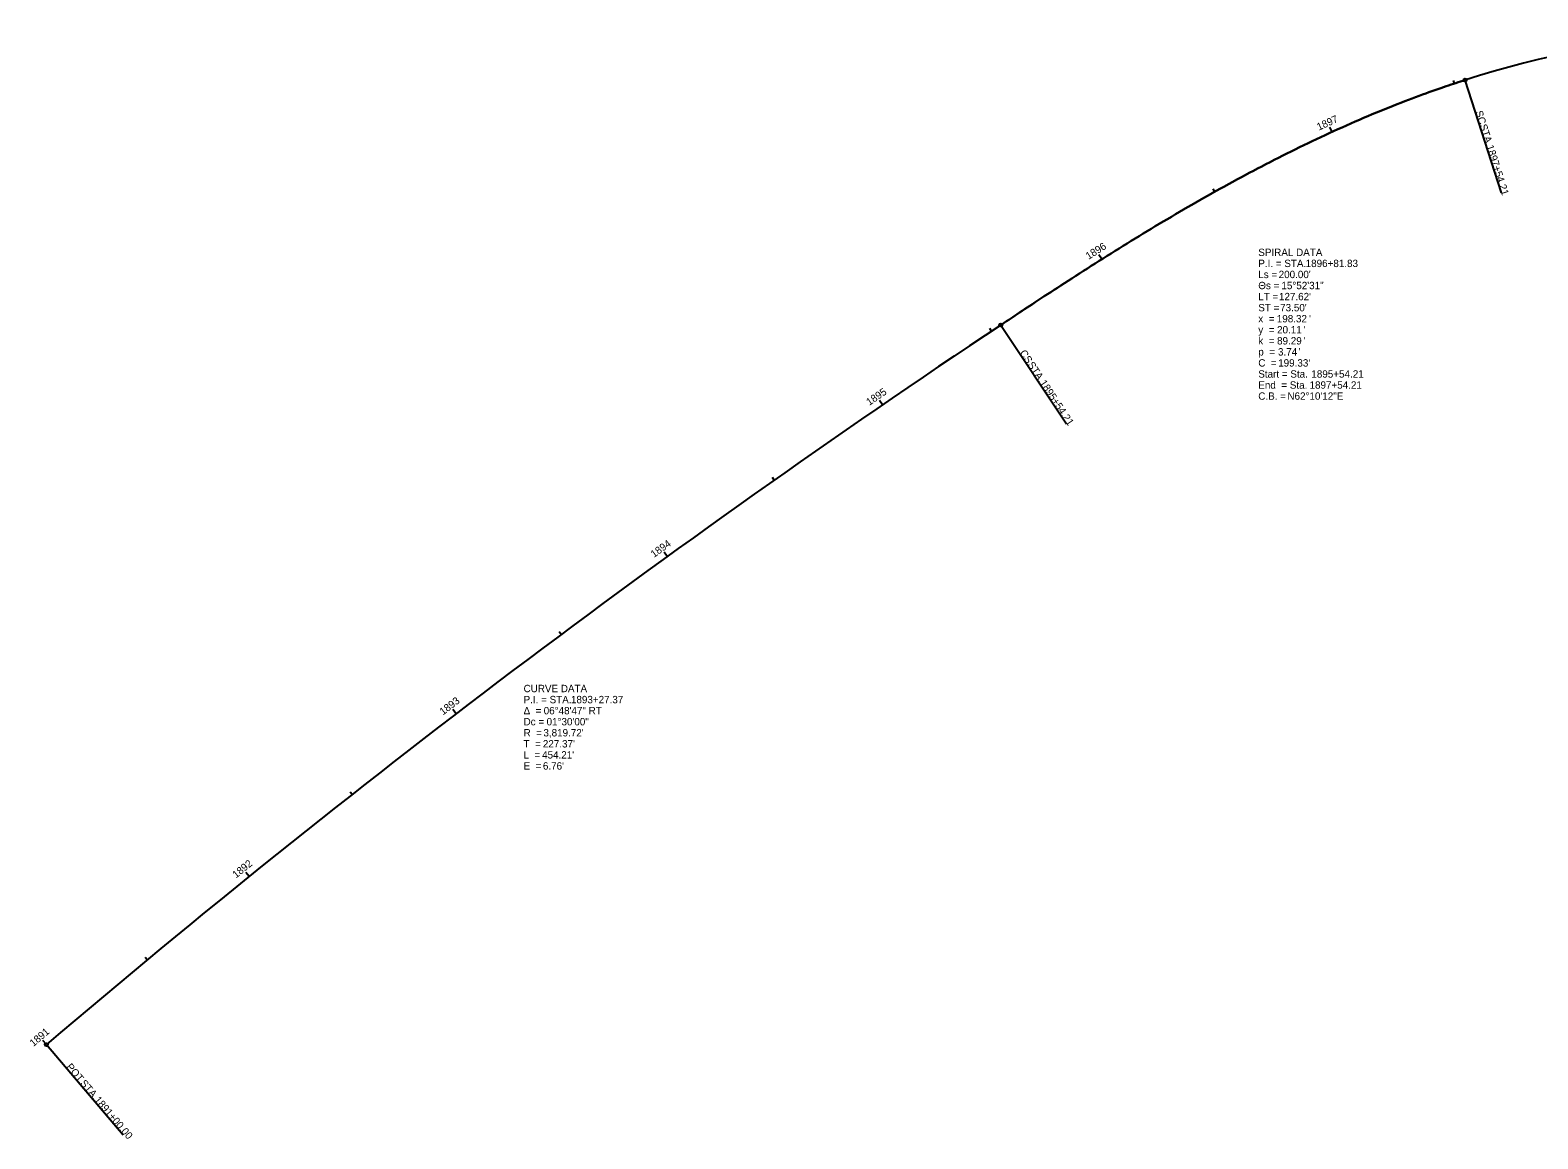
# Model space of a CAD drawing. Extents: x 200995 to 202108, y 391921 to 392784.
# Drawn here: x 200995 to 201568, y 392358 to 392779 of the extents above; entities that cross this region are included whole.
import ezdxf

# ---------------------------------------------------------------- set-up
doc = ezdxf.new("R2010")
doc.units = 0
for name, color, linetype in [('_CIVIL_CONSTRUCTION', 7, 'Continuous'), ('Default', 7, 'Continuous'), ('GE_X_Alignment', 7, 'Continuous'), ('GE_X_Alignment_100_Bearings', 7, 'Continuous'), ('SV_X_Mon_Cells_Found_Text', 7, 'Continuous')]:
    doc.layers.add(name, color=color, linetype=linetype)

msp = doc.modelspace()

# ---------------------------------------------------------------- linework, layer by layer
at = {"layer": '_CIVIL_CONSTRUCTION'}
for centre, radius, start, end in [((201661.28, 392380.6), 398.57, 2.7335, 107.7438), ((203478.39, 389486.33), 3819.72, 123.61908, 130.43223)]:
    msp.add_arc(centre, radius, start, end, dxfattribs=at)
msp.add_open_spline([(201363.53, 392667.15), (201365.52, 392668.47), (201369.48, 392671.1), (201377.43, 392676.35), (201387.4, 392682.86), (201399.42, 392690.58), (201411.53, 392698.17), (201423.73, 392705.6), (201436.04, 392712.84), (201448.48, 392719.87), (201461.05, 392726.65), (201473.78, 392733.15), (201486.65, 392739.34), (201499.69, 392745.18), (201512.89, 392750.65), (201524.03, 392754.85), (201533.02, 392757.99), (201537.54, 392759.49), (201539.81, 392760.21)], degree=3, dxfattribs=at)
at = {"layer": 'Default'}
msp.add_arc((203478.39, 389486.33), 3819.72, 123.61908, 130.43223, dxfattribs=at)
msp.add_open_spline([(201539.81, 392760.21), (201537.54, 392759.49), (201533.02, 392757.99), (201524.03, 392754.85), (201512.89, 392750.65), (201499.69, 392745.18), (201486.65, 392739.34), (201473.78, 392733.15), (201461.05, 392726.65), (201448.48, 392719.87), (201436.04, 392712.84), (201423.73, 392705.6), (201411.53, 392698.17), (201399.42, 392690.58), (201387.4, 392682.86), (201377.43, 392676.35), (201369.48, 392671.1), (201365.52, 392668.47), (201363.53, 392667.15)], degree=3, dxfattribs=at)
at = {"layer": 'GE_X_Alignment'}
for p, q in [((201539.81, 392760.21), (201553.53, 392717.35)), ((201363.53, 392667.15), (201388.45, 392629.68)), ((201001.12, 392393.8), (201030.31, 392359.55))]:
    msp.add_line(p, q, dxfattribs=at)
for centre in [(201539.81, 392760.21), (201363.53, 392667.15), (201001.12, 392393.8)]:
    msp.add_circle(centre, 0.6, dxfattribs=at)
at = {"layer": 'GE_X_Alignment_100_Bearings'}
for p, q in [((201535.81, 392758.91), (201535.43, 392760.05)), ((201489.34, 392740.51), (201488.51, 392742.33)), ((201444.82, 392717.78), (201444.24, 392718.83)), ((201401.91, 392692.13), (201400.85, 392693.82)), ((201360.03, 392664.82), (201359.36, 392665.82)), ((201318.61, 392636.82), (201317.48, 392638.47)), ((201277.55, 392608.28), (201276.86, 392609.26)), ((201236.88, 392579.2), (201235.7, 392580.82)), ((201196.58, 392549.6), (201195.87, 392550.56)), ((201156.68, 392519.47), (201155.47, 392521.06)), ((201117.18, 392488.82), (201116.44, 392489.76)), ((201078.08, 392457.65), (201076.82, 392459.21)), ((201039.39, 392425.98), (201038.63, 392426.9)), ((201001.12, 392393.8), (200999.82, 392395.32))]:
    msp.add_line(p, q, dxfattribs=at)

# ---------------------------------------------------------------- texts
at = {"layer": 'GE_X_Alignment'}
for s, rotation, p in [('SC', 287.7438, (201543.72, 392748.12)), (' STA. ', 287.7438, (201545.05, 392743.97)), ('1897+54.21', 287.7438, (201547.89, 392735.09)), ('CS', 303.6191, (201370.6, 392656.59)), (' STA. ', 303.6191, (201373.02, 392652.96)), ('1895+54.21', 303.6191, (201378.18, 392645.2)), ('POT', 310.4322, (201008.47, 392385.24)), (' STA. ', 310.4322, (201013.09, 392379.81)), ('1891+00.00', 310.4322, (201019.14, 392372.72))]:
    msp.add_text(s, height=2.8, rotation=rotation, dxfattribs=at).set_placement(p)
at = {"layer": 'GE_X_Alignment_100_Bearings'}
for s, rotation, p in [('1897', 24.5907, (201484.34, 392740.97)), ('1896', 32.2573, (201396.88, 392691.91)), ('1895', 34.4322, (201313.63, 392636.44)), ('1894', 35.9322, (201231.85, 392578.65)), ('1893', 37.4322, (201151.74, 392518.83)), ('1892', 38.9322, (201073.14, 392456.88)), ('1891', 40.4322, (200996.2, 392392.89))]:
    msp.add_text(s, height=2.8, rotation=rotation, dxfattribs=at).set_placement(p)
at = {"layer": 'SV_X_Mon_Cells_Found_Text'}
for s, p in [('SPIRAL DATA', (201461.34, 392693.37)), ('P.I. = STA. ', (201461.34, 392689.17)), ('Ls = ', (201461.34, 392684.97)), ("200.00'", (201469.08, 392684.97)), ('1896+81.83', (201479.33, 392689.17)), ('Θs = ', (201461.34, 392680.77)), ('15°52\'31"', (201470.12, 392680.77)), ('ST = ', (201461.34, 392672.37)), ('LT = ', (201461.34, 392676.57)), ("127.62'", (201469.19, 392676.57)), ("73.50'", (201469.64, 392672.37)), ('x  = ', (201461.34, 392668.17)), ('198.32', (201468.37, 392668.17)), ("'", (201480.62, 392668.17)), ('y  = ', (201461.34, 392663.97)), ('20.11', (201468.47, 392663.97)), ("'", (201478.49, 392663.97)), ('k  = ', (201461.34, 392659.77)), ('89.29', (201468.47, 392659.77)), ('3.74', (201468.82, 392655.57)), ("'", (201476.6, 392655.57)), ("'", (201478.49, 392659.77)), ('C  = ', (201461.34, 392651.37)), ('p  = ', (201461.34, 392655.57)), ("199.33'", (201468.89, 392651.37)), ('Start = Sta. ', (201461.34, 392647.17)), ('1895+54.21', (201481.49, 392647.17)), ('C.B. = ', (201461.34, 392638.77)), ('End  = Sta. ', (201461.34, 392642.97)), ('N62°10\'12"E', (201472.41, 392638.77)), ('1897+54.21', (201480.8, 392642.97)), ('CURVE DATA', (201182.33, 392527.68)), ('P.I. = STA. ', (201182.33, 392523.48)), ('1893+27.37', (201200.32, 392523.48)), ('Δ  = ', (201182.33, 392519.28)), ('06°48\'47" RT', (201189.97, 392519.28)), ('Dc = ', (201182.33, 392515.08)), ('01°30\'00"', (201191.07, 392515.08)), ('T  = ', (201182.33, 392506.68)), ('R  = ', (201182.33, 392510.88)), ("227.37'", (201189.65, 392506.68)), ("3,819.72'", (201189.86, 392510.88)), ('L  = ', (201182.33, 392502.48)), ("454.21'", (201189.36, 392502.48)), ('E  = ', (201182.33, 392498.28)), ("6.76'", (201189.67, 392498.28))]:
    msp.add_text(s, height=2.8, dxfattribs=at).set_placement(p)

doc.saveas('drawing.dxf')
